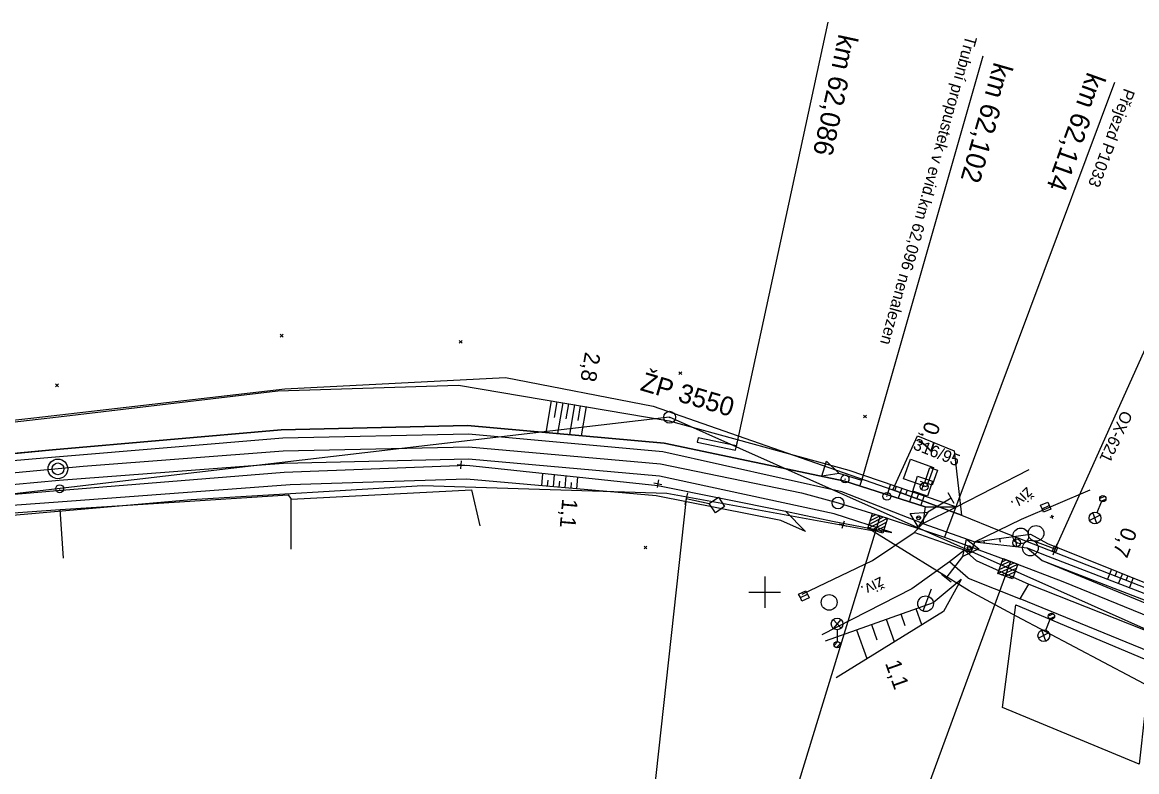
# Model space of a CAD drawing. Extents: x -805636 to -804553, y -1165340 to -1164656.
# Drawn here: x -805494.5 to -805352.6, y -1164922.9 to -1164827.5 of the extents above; entities that cross this region are included whole.
import ezdxf

# ---------------------------------------------------------------- set-up
doc = ezdxf.new("R2010")
doc.units = 0
for name, color, linetype in [('0381KM061-064P - Vrstva 1', 7, 'Continuous'), ('0381KM061-064P - Vrstva 12', 7, 'Continuous'), ('0381KM061-064P - Vrstva 16', 7, 'Continuous'), ('0381KM061-064P - Vrstva 17', 7, 'Continuous'), ('0381KM061-064P - Vrstva 19', 7, 'Continuous'), ('0381KM061-064P - Vrstva 23', 7, 'Continuous'), ('0381KM061-064P - Vrstva 25', 7, 'Continuous'), ('0381KM061-064P - Vrstva 27', 7, 'Continuous'), ('0381KM061-064P - Vrstva 3', 7, 'Continuous'), ('0381KM061-064P - Vrstva 33', 7, 'Continuous'), ('0381KM061-064P - Vrstva 4', 7, 'Continuous'), ('0381KM061-064P - Vrstva 43', 7, 'Continuous'), ('0381KM061-064P - Vrstva 48', 7, 'Continuous'), ('0381KM061-064P - Vrstva 49', 7, 'Continuous'), ('0381KM061-064P - Vrstva 51', 7, 'Continuous'), ('0381KM061-064P - Vrstva 55', 7, 'Continuous'), ('0381KM061-064P - Vrstva 57', 7, 'Continuous'), ('0381KM061-064P - Vrstva 7', 7, 'Continuous'), ('0381KM061-064P - Vrstva 8', 7, 'Continuous'), ('0381KM061-064P - Vrstva 9', 7, 'Continuous'), ('hran DP - hran DP', 7, 'Continuous'), ('krizky_1000 - Vrstva 1', 7, 'Continuous'), ('vyt_sit - polygon', 7, 'Continuous'), ('vyt_sit - stávající', 7, 'Continuous')]:
    doc.layers.add(name, color=color, linetype=linetype)

msp = doc.modelspace()

# ---------------------------------------------------------------- linework, layer by layer
at = {"layer": '0381KM061-064P - Vrstva 1'}
msp.add_line((-805413.27, -1164883.66), (-805395.31, -1164887.39), dxfattribs=at)
for points in [[(-805621.7, -1164896.48), (-805615.58, -1164895.98), (-805590.01, -1164893.62), (-805528.48, -1164887.9), (-805486.76, -1164883.98), (-805461.3, -1164882.03), (-805437.69, -1164881.51), (-805413.27, -1164883.66)], [(-805395.31, -1164887.39), (-805390.66, -1164888.66), (-805385.3, -1164890.3), (-805377.11, -1164893.01), (-805368.7, -1164896.09), (-805362.07, -1164898.64)], [(-805362.07, -1164898.64), (-805347.39, -1164904.64), (-805344.65, -1164905.78)]]:
    msp.add_lwpolyline(points, dxfattribs=at)
at = {"layer": '0381KM061-064P - Vrstva 12'}
for p, q in [((-805363.35, -1164894.76), (-805363.11, -1164894.15)), ((-805362.92, -1164894.93), (-805362.69, -1164894.32)), ((-805362.92, -1164894.93), (-805362.69, -1164894.32))]:
    msp.add_line(p, q, dxfattribs=at)
for points in [[(-805363.35, -1164894.76), (-805363.35, -1164894.76), (-805363.11, -1164894.15), (-805363.11, -1164894.15), (-805362.69, -1164894.32), (-805362.69, -1164894.32), (-805363.11, -1164894.15)], [(-805363.35, -1164894.76), (-805362.92, -1164894.93), (-805362.92, -1164894.93), (-805363.35, -1164894.76)]]:
    msp.add_lwpolyline(points, dxfattribs=at)
at = {"layer": '0381KM061-064P - Vrstva 16'}
msp.add_lwpolyline([(-805366.38, -1164898.98), (-805348.12, -1164906.22), (-805348.61, -1164907.57), (-805349.09, -1164908.36), (-805367.46, -1164900.88), (-805366.38, -1164898.98)], dxfattribs=at)
at = {"layer": '0381KM061-064P - Vrstva 17'}
for p, q in [((-805460.29, -1164894.52), (-805460.29, -1164888.19)), ((-805489.25, -1164895.68), (-805489.69, -1164889.49))]:
    msp.add_line(p, q, dxfattribs=at)
for points in [[(-805536.86, -1164897.86), (-805537.37, -1164893.17), (-805513.54, -1164891.19), (-805489.69, -1164889.49), (-805460.65, -1164887.61), (-805460.29, -1164888.19), (-805437.32, -1164886.99), (-805436.25, -1164891.59)], [(-805369.75, -1164914.7), (-805368.04, -1164901.63), (-805350.89, -1164908.84), (-805352.32, -1164921.91), (-805369.75, -1164914.7)]]:
    msp.add_lwpolyline(points, dxfattribs=at)
at = {"layer": '0381KM061-064P - Vrstva 23'}
msp.add_lwpolyline([(-805382.32, -1164885.58), (-805381.44, -1164883.1), (-805378.52, -1164884.13), (-805379.4, -1164886.61)], close=True, dxfattribs=at)
at = {"layer": '0381KM061-064P - Vrstva 25'}
for p, q in [((-805356.71, -1164887.82), (-805357.36, -1164888.1)), ((-805357.68, -1164889.88), (-805357.11, -1164888.5)), ((-805356.57, -1164888.2), (-805357.18, -1164888.45)), ((-805357.3, -1164890.23), (-805358.64, -1164890.89)), ((-805357.72, -1164891.28), (-805358.22, -1164889.87)), ((-805363.25, -1164902.78), (-805363.9, -1164903.06)), ((-805363.11, -1164903.15), (-805363.72, -1164903.42)), ((-805391.28, -1164903.49), (-805390.28, -1164904.6)), ((-805391.26, -1164904.62), (-805390.28, -1164903.5)), ((-805390.78, -1164904.8), (-805390.78, -1164906.3)), ((-805364.22, -1164906.25), (-805364.74, -1164904.85)), ((-805364.2, -1164904.85), (-805363.65, -1164903.45)), ((-805363.82, -1164905.19), (-805365.15, -1164905.87)), ((-805391.17, -1164906.78), (-805390.7, -1164906.31)), ((-805390.9, -1164907.08), (-805390.4, -1164906.58))]:
    msp.add_line(p, q, dxfattribs=at)
msp.add_lwpolyline([(-805378.69, -1164886.38), (-805379.63, -1164886.05), (-805378.96, -1164884.16), (-805378.02, -1164884.5), (-805378.69, -1164886.38)], dxfattribs=at)
for centre, radius in [((-805356.96, -1164888.12), 0.4), ((-805356.96, -1164888.12), 0.4), ((-805357.96, -1164890.58), 0.749), ((-805390.78, -1164904.05), 0.749), ((-805363.5, -1164903.08), 0.4), ((-805363.5, -1164903.08), 0.4), ((-805364.47, -1164905.55), 0.749), ((-805390.78, -1164906.7), 0.4), ((-805390.78, -1164906.7), 0.4)]:
    msp.add_circle(centre, radius, dxfattribs=at)
at = {"layer": '0381KM061-064P - Vrstva 27'}
for p, q in [((-805384.49, -1164887.81), (-805384.39, -1164887.81)), ((-805379.67, -1164886.61), (-805379.76, -1164886.58)), ((-805367.98, -1164893.73), (-805367.88, -1164893.73))]:
    msp.add_line(p, q, dxfattribs=at)
for centre in [(-805379.71, -1164886.59), (-805384.44, -1164887.81), (-805367.93, -1164893.73)]:
    msp.add_circle(centre, 0.5, dxfattribs=at)
at = {"layer": '0381KM061-064P - Vrstva 3'}
for p, q in [((-805385.3, -1164890.3), (-805402.6, -1164946.88)), ((-805386.87, -1164891.9), (-805384.35, -1164890.6)), ((-805386.7, -1164891.39), (-805384.86, -1164890.44)), ((-805386.54, -1164890.89), (-805385.36, -1164890.28)), ((-805386.38, -1164890.38), (-805385.87, -1164890.12)), ((-805386.36, -1164892.06), (-805384.51, -1164891.11)), ((-805385.86, -1164892.22), (-805384.67, -1164891.61)), ((-805385.35, -1164892.38), (-805384.84, -1164892.12)), ((-805368.7, -1164896.09), (-805389.1, -1164951.65)), ((-805370.16, -1164897.12), (-805368.26, -1164896.26)), ((-805369.97, -1164896.62), (-805368.76, -1164896.07)), ((-805369.78, -1164896.13), (-805369.26, -1164895.89)), ((-805370.34, -1164897.62), (-805367.77, -1164896.44)), ((-805369.85, -1164897.8), (-805367.95, -1164896.94)), ((-805369.35, -1164897.99), (-805368.14, -1164897.44)), ((-805368.85, -1164898.17), (-805368.33, -1164897.93))]:
    msp.add_line(p, q, dxfattribs=at)
for points in [[(-805386.26, -1164889.99), (-805384.35, -1164890.6), (-805384.96, -1164892.51), (-805386.87, -1164891.9)], [(-805369.64, -1164895.74), (-805367.77, -1164896.44), (-805368.47, -1164898.32), (-805370.34, -1164897.62)]]:
    msp.add_lwpolyline(points, close=True, dxfattribs=at)
at = {"layer": '0381KM061-064P - Vrstva 33'}
for p, q in [((-805380.22, -1164885.9), (-805379.27, -1164886.21)), ((-805379.74, -1164886.05), (-805380.06, -1164887))]:
    msp.add_line(p, q, dxfattribs=at)
msp.add_lwpolyline([(-805380.53, -1164885.26), (-805378.63, -1164885.89), (-805379.26, -1164887.79), (-805381.16, -1164887.16), (-805380.53, -1164885.26)], dxfattribs=at)
at = {"layer": '0381KM061-064P - Vrstva 4'}
for p, q in [((-805355.47, -1164835.15), (-805377.11, -1164893.01)), ((-805461.56, -1164879.34), (-805437.82, -1164878.81)), ((-805437.82, -1164878.81), (-805412.78, -1164881.05)), ((-805490.63, -1164881.9), (-805461.56, -1164879.34)), ((-805461.35, -1164880.4), (-805490.28, -1164882.82)), ((-805437.68, -1164879.9), (-805461.35, -1164880.4)), ((-805412.96, -1164882.16), (-805437.68, -1164879.9)), ((-805528.63, -1164885.47), (-805490.63, -1164881.9)), ((-805390.18, -1164887.25), (-805412.96, -1164882.16)), ((-805412.78, -1164881.05), (-805389.79, -1164885.89)), ((-805490.28, -1164882.82), (-805528.62, -1164886.23)), ((-805379.87, -1164891.27), (-805390.18, -1164887.25)), ((-805375.87, -1164888.73), (-805376.65, -1164887.39)), ((-805380.17, -1164890.61), (-805380.65, -1164890.49)), ((-805374.21, -1164894.39), (-805373.72, -1164894.33)), ((-805377.5, -1164897.74), (-805376.27, -1164898.69))]:
    msp.add_line(p, q, dxfattribs=at)
for points in [[(-805383.82, -1164892.41), (-805391.14, -1164890.05), (-805413.4, -1164885.24), (-805437.69, -1164883.08), (-805461.24, -1164883.62), (-805489.81, -1164885.79), (-805528.46, -1164889.37), (-805589.94, -1164895), (-805615.48, -1164897.55), (-805622.38, -1164898.08)], [(-805622.83, -1164899.13), (-805615.58, -1164898.49), (-805589.92, -1164896.02), (-805528.49, -1164890.34), (-805490.03, -1164887.06), (-805461.18, -1164884.75), (-805437.91, -1164883.87), (-805413.61, -1164886.43), (-805397.33, -1164889.69), (-805391.36, -1164890.97), (-805383.82, -1164892.41)], [(-805389.79, -1164885.89), (-805379.56, -1164889.14), (-805379.87, -1164891.27)], [(-805376.26, -1164888.06), (-805379.25, -1164889.83), (-805380.48, -1164891.7), (-805381.5, -1164889.98), (-805379.25, -1164889.83)], [(-805380.99, -1164892.42), (-805379.87, -1164891.27), (-805373.25, -1164893.62), (-805373.77, -1164894.98), (-805380.99, -1164892.42)], [(-805376.89, -1164898.22), (-805374.77, -1164895.46), (-805374.33, -1164893.27), (-805372.74, -1164894.48), (-805374.77, -1164895.46)], [(-805364.7, -1164895.97), (-805343.19, -1164904.86), (-805317.03, -1164915.68), (-805296.75, -1164924.42), (-805284.83, -1164929.56), (-805254.7, -1164942.26), (-805226.16, -1164954.55), (-805203.52, -1164964.18), (-805187.57, -1164970.92)], [(-805364.7, -1164895.97), (-805342.91, -1164904.36), (-805316.81, -1164915.12), (-805296.46, -1164924.13), (-805284.52, -1164929.13), (-805254.45, -1164941.83), (-805225.92, -1164953.93), (-805203.38, -1164963.47), (-805187.4, -1164970.45)]]:
    msp.add_lwpolyline(points, dxfattribs=at)
for centre in [(-805380.41, -1164890.55), (-805373.96, -1164894.36)]:
    msp.add_circle(centre, 0.248, dxfattribs=at)
at = {"layer": '0381KM061-064P - Vrstva 43'}
msp.add_line((-805378.82, -1164899.61), (-805379.87, -1164902.41), dxfattribs=at)
for points in [[(-805364.7, -1164889.39), (-805364.89, -1164888.94), (-805363.98, -1164888.54), (-805363.58, -1164889.46), (-805364.5, -1164889.85), (-805364.7, -1164889.39), (-805363.78, -1164889)], [(-805395.46, -1164900.7), (-805395.68, -1164900.25), (-805394.78, -1164899.82), (-805394.35, -1164900.72), (-805395.25, -1164901.15), (-805395.46, -1164900.7), (-805394.56, -1164900.27)]]:
    msp.add_lwpolyline(points, dxfattribs=at)
for centre, radius in [((-805391.79, -1164901.31), 1), ((-805379.52, -1164901.48), 0.996)]:
    msp.add_circle(centre, radius, dxfattribs=at)
at = {"layer": '0381KM061-064P - Vrstva 48'}
for p, q in [((-805427.18, -1164875.65), (-805427.86, -1164879.7)), ((-805426.44, -1164875.78), (-805426.78, -1164877.77)), ((-805425.7, -1164875.9), (-805426.36, -1164879.83)), ((-805424.96, -1164876.03), (-805425.29, -1164877.96)), ((-805424.22, -1164876.15), (-805424.86, -1164879.97)), ((-805423.48, -1164876.28), (-805423.8, -1164878.16)), ((-805422.74, -1164876.4), (-805423.37, -1164880.1)), ((-805428.38, -1164886.47), (-805428.24, -1164884.89)), ((-805427.64, -1164886.54), (-805427.57, -1164885.75)), ((-805426.89, -1164886.61), (-805426.75, -1164885.04)), ((-805426.14, -1164886.67), (-805426.07, -1164885.9)), ((-805425.39, -1164886.74), (-805425.26, -1164885.2)), ((-805424.65, -1164886.8), (-805424.58, -1164886.04)), ((-805423.9, -1164886.87), (-805423.77, -1164885.36)), ((-805383.98, -1164886.28), (-805384.43, -1164887.59)), ((-805383.27, -1164886.53), (-805383.49, -1164887.17)), ((-805382.56, -1164886.77), (-805383, -1164888.05)), ((-805381.85, -1164887.01), (-805382.07, -1164887.64)), ((-805381.14, -1164887.25), (-805381.57, -1164888.5)), ((-805380.43, -1164887.49), (-805380.64, -1164888.11)), ((-805379.72, -1164887.73), (-805380.14, -1164888.96)), ((-805372.01, -1164893.76), (-805372.05, -1164893.46)), ((-805370, -1164893.66), (-805370.07, -1164893.18)), ((-805367.91, -1164894.21), (-805368.1, -1164892.9)), ((-805355.86, -1164897.08), (-805356.37, -1164898.34)), ((-805355.16, -1164897.36), (-805355.42, -1164897.99)), ((-805354.47, -1164897.64), (-805354.97, -1164898.88)), ((-805353.77, -1164897.92), (-805354.02, -1164898.54)), ((-805353.08, -1164898.2), (-805353.57, -1164899.43)), ((-805382.1, -1164904.28), (-805382.62, -1164902.82)), ((-805380.01, -1164904.18), (-805380.73, -1164902.15)), ((-805386.96, -1164908.48), (-805388.26, -1164904.83)), ((-805385.69, -1164906.1), (-805386.38, -1164904.16)), ((-805383.49, -1164906.33), (-805384.5, -1164903.49))]:
    msp.add_line(p, q, dxfattribs=at)
at = {"layer": '0381KM061-064P - Vrstva 49'}
for p, q in [((-805461.3, -1164867.54), (-805461.65, -1164867.18)), ((-805461.3, -1164867.18), (-805461.65, -1164867.54)), ((-805438.52, -1164868.33), (-805438.87, -1164867.98)), ((-805438.52, -1164867.98), (-805438.87, -1164868.33)), ((-805410.56, -1164872.33), (-805410.91, -1164871.98)), ((-805410.56, -1164871.98), (-805410.91, -1164872.33)), ((-805489.9, -1164873.86), (-805490.25, -1164873.51)), ((-805489.9, -1164873.51), (-805490.25, -1164873.86)), ((-805387.06, -1164877.83), (-805387.41, -1164877.47)), ((-805387.06, -1164877.47), (-805387.41, -1164877.83)), ((-805363.68, -1164890.45), (-805363.19, -1164890.34)), ((-805363.49, -1164890.15), (-805363.38, -1164890.64)), ((-805366.17, -1164892.62), (-805364.02, -1164893.8)), ((-805414.99, -1164894.49), (-805415.34, -1164894.14)), ((-805414.99, -1164894.14), (-805415.34, -1164894.49)), ((-805366.61, -1164894.35), (-805364.49, -1164895.2))]:
    msp.add_line(p, q, dxfattribs=at)
for points in [[(-805619.35, -1164890.95), (-805615.91, -1164890.53), (-805590.56, -1164886.39), (-805529.03, -1164882.21), (-805489.9, -1164877.68), (-805461.98, -1164874.39), (-805438.96, -1164873.66), (-805412.14, -1164878.2), (-805389.29, -1164884.48), (-805375.6, -1164889.14)], [(-805379.56, -1164889.14), (-805389.79, -1164885.89), (-805412.78, -1164881.05), (-805437.82, -1164878.81), (-805461.56, -1164879.34), (-805490.63, -1164881.9), (-805528.63, -1164885.47), (-805589.69, -1164890.91), (-805616.18, -1164893.18), (-805620.48, -1164893.61)], [(-805622.83, -1164899.13), (-805615.58, -1164898.49), (-805589.92, -1164896.02), (-805528.49, -1164890.34), (-805490.03, -1164887.06), (-805461.18, -1164884.75), (-805437.91, -1164883.87), (-805413.61, -1164886.43), (-805397.33, -1164889.69), (-805394.79, -1164892.28)], [(-805394.79, -1164892.28), (-805397.93, -1164890.9), (-805413.8, -1164887.77), (-805437.96, -1164885.62), (-805460.38, -1164886.37), (-805489.93, -1164888.57), (-805513.35, -1164890.24), (-805537.4, -1164892.44), (-805590.64, -1164897.22), (-805615.62, -1164899.61), (-805623.38, -1164900.43)], [(-805379.56, -1164889.14), (-805375.6, -1164889.14)], [(-805373.25, -1164893.62), (-805366.17, -1164892.62)], [(-805373.25, -1164893.62), (-805366.61, -1164894.35)], [(-805366.61, -1164894.35), (-805364.7, -1164895.97), (-805342.91, -1164904.36), (-805316.81, -1164915.12), (-805296.46, -1164924.13)], [(-805364.02, -1164893.8), (-805346.07, -1164901.02), (-805315.87, -1164912.66), (-805295.19, -1164922.01)], [(-805364.49, -1164895.2), (-805347.1, -1164901.93), (-805316.44, -1164914.01), (-805295.94, -1164922.85)], [(-805374.97, -1164898.41), (-805378.55, -1164901.37), (-805392.29, -1164906.26)], [(-805374.97, -1164898.41), (-805377.24, -1164902.47), (-805390.88, -1164910.9)]]:
    msp.add_lwpolyline(points, dxfattribs=at)
at = {"layer": '0381KM061-064P - Vrstva 51'}
for p, q in [((-805380.99, -1164892.42), (-805379.87, -1164891.27)), ((-805373.06, -1164895.99), (-805366.38, -1164898.98)), ((-805374.09, -1164898.25), (-805367.46, -1164900.88))]:
    msp.add_line(p, q, dxfattribs=at)
for points in [[(-805379.87, -1164891.27), (-805375.6, -1164889.14), (-805366.34, -1164884.42)], [(-805373.25, -1164893.62), (-805367.29, -1164890.73), (-805358.55, -1164886.97)], [(-805395.22, -1164900.25), (-805386.26, -1164896), (-805380.99, -1164892.42)], [(-805374.56, -1164894.67), (-805376.47, -1164896.14), (-805381.29, -1164899.6), (-805392.72, -1164905.44)], [(-805374.56, -1164894.67), (-805373.77, -1164894.98), (-805373.25, -1164893.62)], [(-805373.06, -1164895.99), (-805374.56, -1164894.67)], [(-805374.09, -1164898.25), (-805376.47, -1164896.14)]]:
    msp.add_lwpolyline(points, dxfattribs=at)
at = {"layer": '0381KM061-064P - Vrstva 55'}
msp.add_lwpolyline([(-805383.69, -1164886.97), (-805380.55, -1164880.12), (-805375.86, -1164882.04), (-805375.28, -1164887.22), (-805374.94, -1164890.22)], close=True, dxfattribs=at)
at = {"layer": '0381KM061-064P - Vrstva 7'}
for p, q in [((-805438.62, -1164883.31), (-805438.7, -1164884.31)), ((-805439.16, -1164883.76), (-805438.16, -1164883.85)), ((-805414.09, -1164886.11), (-805413.11, -1164886.31)), ((-805413.5, -1164885.72), (-805413.7, -1164886.7)), ((-805389.82, -1164885.59), (-805389.72, -1164885.62)), ((-805489.78, -1164886.86), (-805489.68, -1164886.85)), ((-805390.5, -1164891.3), (-805389.54, -1164891.6)), ((-805389.87, -1164890.97), (-805390.17, -1164891.93))]:
    msp.add_line(p, q, dxfattribs=at)
for centre, radius in [((-805489.96, -1164884.32), 1.25), ((-805489.96, -1164884.32), 0.752), ((-805489.73, -1164886.85), 0.5), ((-805389.77, -1164885.6), 0.5), ((-805390.66, -1164888.66), 0.75)]:
    msp.add_circle(centre, radius, dxfattribs=at)
at = {"layer": '0381KM061-064P - Vrstva 8'}
for p, q in [((-805387.65, -1164885.82), (-805372.19, -1164831.77)), ((-805363.02, -1164894.54), (-805338.8, -1164840.62)), ((-805392.11, -1164883.34), (-805390.51, -1164884.9)), ((-805387.88, -1164886.53), (-805387.42, -1164885.1)), ((-805409.84, -1164887.37), (-805410.15, -1164888.84)), ((-805410, -1164888.1), (-805416.33, -1164945.95)), ((-805363.02, -1164894.54), (-805365.82, -1164893.46)), ((-805363.28, -1164895.24), (-805362.75, -1164893.84))]:
    msp.add_line(p, q, dxfattribs=at)
for points in [[(-805387.65, -1164885.82), (-805390.51, -1164884.9), (-805392.72, -1164885.24), (-805392.11, -1164883.34), (-805390.51, -1164884.9)], [(-805410, -1164888.1), (-805407.06, -1164888.71), (-805405.88, -1164887.94), (-805405.1, -1164889.12), (-805406.28, -1164889.9), (-805407.06, -1164888.71)]]:
    msp.add_lwpolyline(points, dxfattribs=at)
for centre in [(-805367.4, -1164892.85), (-805365.46, -1164892.53), (-805366.18, -1164894.4)]:
    msp.add_circle(centre, 1, dxfattribs=at)
at = {"layer": '0381KM061-064P - Vrstva 9'}
for p, q in [((-805403.65, -1164881.66), (-805391.9, -1164827.49)), ((-805408.48, -1164880.35), (-805408.6, -1164880.94)), ((-805403.58, -1164881.37), (-805408.48, -1164880.35)), ((-805408.6, -1164880.94), (-805403.71, -1164881.96)), ((-805403.71, -1164881.96), (-805403.58, -1164881.37)), ((-805403.58, -1164881.37), (-805403.46, -1164880.78))]:
    msp.add_line(p, q, dxfattribs=at)
at = {"layer": 'hran DP - hran DP'}
for p, q in [((-805461.06, -1164874.13), (-805433.01, -1164872.7)), ((-805433.01, -1164872.7), (-805414.19, -1164876.33)), ((-805493.02, -1164877.83), (-805461.06, -1164874.13)), ((-805414.19, -1164876.33), (-805383.69, -1164886.97)), ((-805559.43, -1164885.25), (-805493.02, -1164877.83)), ((-805443.5, -1164886.48), (-805472.98, -1164888.24)), ((-805412.47, -1164887.44), (-805443.5, -1164886.48)), ((-805386.3, -1164892.2), (-805412.47, -1164887.44)), ((-805383.69, -1164886.97), (-805374.94, -1164890.22)), ((-805472.98, -1164888.24), (-805537.37, -1164893.92)), ((-805374.94, -1164890.22), (-805370.14, -1164892.15)), ((-805373.99, -1164899.86), (-805386.3, -1164892.2)), ((-805370.14, -1164892.15), (-805367.78, -1164893.1)), ((-805367.78, -1164893.1), (-805249.75, -1164939.24)), ((-805367.9, -1164903.11), (-805373.99, -1164899.86)), ((-805346.65, -1164914.36), (-805367.9, -1164903.11))]:
    msp.add_line(p, q, dxfattribs=at)
at = {"layer": 'krizky_1000 - Vrstva 1'}
for points in [[(-805400, -1164898), (-805400, -1164902)], [(-805402, -1164900), (-805398, -1164900)]]:
    msp.add_lwpolyline(points, dxfattribs=at)
at = {"layer": 'vyt_sit - polygon'}
for p, q in [((-805412.1, -1164877.75), (-805553.67, -1164894.32)), ((-805286.72, -1164933.58), (-805412.1, -1164877.75))]:
    msp.add_line(p, q, dxfattribs=at)
at = {"layer": 'vyt_sit - stávající'}
msp.add_line((-805412.14, -1164877.72), (-805412.06, -1164877.77), dxfattribs=at)
msp.add_circle((-805412.1, -1164877.75), 0.756, dxfattribs=at)

# ---------------------------------------------------------------- texts
at = {"layer": '0381KM061-064P - Vrstva 19'}
msp.add_text('Trubní propustek v evid.km 62,096 nenalezen', height=1.5, rotation=254.4208, dxfattribs=at).set_placement((-805374.39, -1164829.09))
at = {"layer": '0381KM061-064P - Vrstva 4'}
for s, height, rotation, p in [('km 62,114', 2.5, 250.3868, (-805358.91, -1164833.71)), ('Přejezd P1033', 1.5, 249.4891, (-805354.24, -1164835.8))]:
    msp.add_text(s, height=height, rotation=rotation, dxfattribs=at).set_placement(p)
at = {"layer": '0381KM061-064P - Vrstva 48'}
for s, rotation, p in [('2,8', 260.3835, (-805422.85, -1164869.38)), ('0,7', 251.1992, (-805379.49, -1164878.14)), ('1,1', 264.9104, (-805425.76, -1164888.06)), ('0,7', 248.8398, (-805354.41, -1164891.6)), ('1,1', 289.5856, (-805384.7, -1164909.05))]:
    msp.add_text(s, height=2, rotation=rotation, dxfattribs=at).set_placement(p)
at = {"layer": '0381KM061-064P - Vrstva 51'}
for rotation, p in [(223.2619, (-805366.61, -1164886.55)), (207.0403, (-805385.24, -1164897.99))]:
    msp.add_text('živ.', height=1.5, rotation=rotation, dxfattribs=at).set_placement(p)
at = {"layer": '0381KM061-064P - Vrstva 57'}
msp.add_text('316/95', height=1.5, rotation=338.4457, dxfattribs=at).set_placement((-805381.22, -1164881.77))
at = {"layer": '0381KM061-064P - Vrstva 8'}
for s, height, rotation, p in [('km 62,102', 2.5, 254.036, (-805370.79, -1164832.46)), ('OX-621', 1.5, 244.7151, (-805354.47, -1164876.78))]:
    msp.add_text(s, height=height, rotation=rotation, dxfattribs=at).set_placement(p)
at = {"layer": '0381KM061-064P - Vrstva 9'}
msp.add_text('km 62,086', height=2.5, rotation=257.7697, dxfattribs=at).set_placement((-805390.56, -1164828.89))
at = {"layer": 'vyt_sit - stávající'}
msp.add_text('ŽP 3550', height=2.4, rotation=343.5611, dxfattribs=at).set_placement((-805415.96, -1164874.28))

doc.saveas('drawing.dxf')
